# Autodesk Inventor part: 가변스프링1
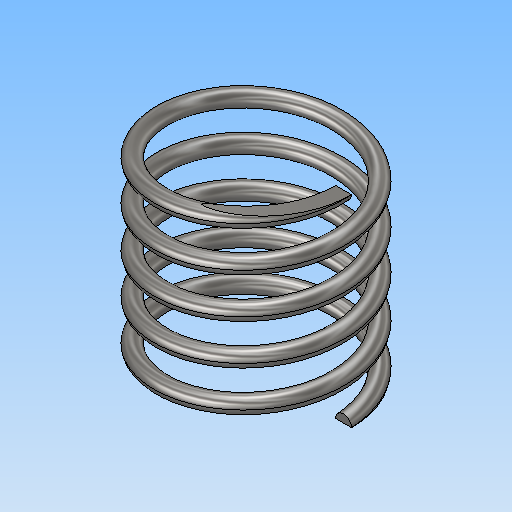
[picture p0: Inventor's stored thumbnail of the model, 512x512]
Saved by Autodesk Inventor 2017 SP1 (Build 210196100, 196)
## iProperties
Part Number: 가변스프링1
Material: 강철, 연강
Document SubType Name: Modeling
Designer: MRC
Density: 7.85 g/cm^3
Appearance: 반연마
Mass: 8.38159 g
Surface Area: 21.6554 cm^2
Volume: 1.06772 cm^3
Author: MRC
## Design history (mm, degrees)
sketch "스케치1"
  geometry: L1 (0, 0)-(0, 25.358); L2 (0, 25.358)-(11, 25.358); L3 (0, 0)-(11, 0); C1 r 1 at (11, 0)
  constraints: 6 end point, 2 horizontal, 1 centre point, 1 coincident, 1 vertical
  dimensions: "d0" = 25.35829 distance of L1.start L1.end (derived); "d1" = 11 distance of L1.end L2.end; "d2" = 22 diameter of L3.end L1; "d3" = 2 diameter of C1
feature "코일1" sketch "스케치1" pitch "d4" = 10; turns "d6" = 5; dims "d5" = 25.35829 (= d0), "d7" = 0, angle "d8" = 90 deg, angle "d9" = 90 deg, "d10" = 0, "d11" = 0
sketch "스케치2"
  geometry: L1 (25.358, 20)-(0, 20); L2 (0, 20)-(0, -20); L3 (0, -20)-(25.358, -20); L4 (25.358, -20)-(25.358, 20); 2 further points
  constraints: 8 end point, 2 parallel, 1 coincident, 1 horizontal, 1 midpoint, 1 perpendicular
  dimensions: "d12" = 25.35829 distance of L2.end L3.end (= d0); "d13" = 40 distance of L3.end L1.start
extrude "돌출1" sketch "스케치2" stored distance "d14" = 0; taper "d15" = 0 deg
node "솔리드1"
